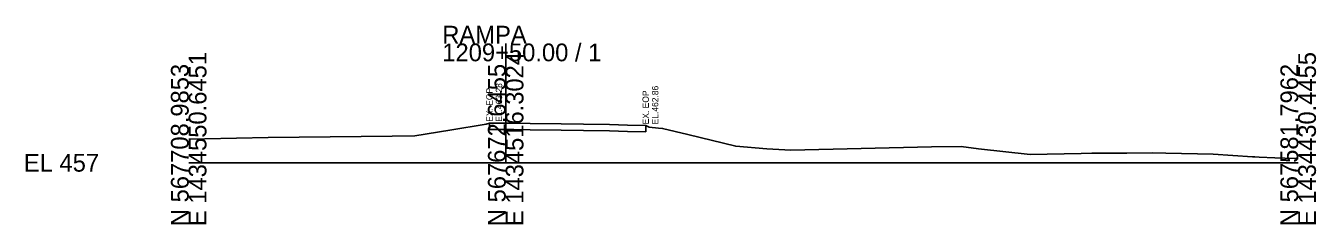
# Model space of a CAD drawing. Extents: x 1431908 to 1449087, y 567604 to 577825.
# Drawn here: x 1432908 to 1433111.5, y 575852.5 to 575883.8 of the extents above; entities that cross this region are included whole.
import ezdxf

# ---------------------------------------------------------------- set-up
doc = ezdxf.new("R2010")
doc.units = 0
for name, color, linetype in [('DESIGN - SHEET - Light Grid', 7, 'Continuous'), ('SURVEY - GROUND - Existing Pavement Layer', 7, 'Continuous'), ('SURVEY - GROUND - Existing Pavement Text', 7, 'Continuous'), ('SURVEY - GROUND - Top of Ground', 7, 'Continuous')]:
    doc.layers.add(name, color=color, linetype=linetype)

msp = doc.modelspace()

# ---------------------------------------------------------------- linework, layer by layer
at = {"layer": 'DESIGN - SHEET - Light Grid'}
for p, q in [((1432983.66, 575862.16), (1432983.66, 575880.98)), ((1432933.66, 575862.16), (1432983.66, 575862.16)), ((1432983.66, 575862.16), (1433108.66, 575862.16))]:
    msp.add_line(p, q, dxfattribs=at)
at = {"layer": 'SURVEY - GROUND - Existing Pavement Layer'}
for p, q in [((1432981.1, 575867.43), (1432981.1, 575868.43)), ((1432981.1, 575867.43), (1432983.66, 575867.42)), ((1432983.66, 575867.42), (1432984.08, 575867.42)), ((1432984.08, 575867.42), (1432984.97, 575867.41)), ((1432984.97, 575867.41), (1432987.51, 575867.38)), ((1432987.51, 575867.38), (1432992.4, 575867.33)), ((1432992.4, 575867.33), (1432995.93, 575867.26)), ((1432995.93, 575867.26), (1433000.05, 575867.19)), ((1433000.05, 575867.19), (1433002.86, 575867.11)), ((1433002.86, 575867.11), (1433005.74, 575867.02)), ((1433005.74, 575868.02), (1433005.74, 575867.02))]:
    msp.add_line(p, q, dxfattribs=at)
at = {"layer": 'SURVEY - GROUND - Top of Ground'}
msp.add_lwpolyline([(1432933.66, 575865.9), (1432936.19, 575865.94), (1432946.21, 575866.13), (1432965.74, 575866.37), (1432969.32, 575866.41), (1432974.85, 575867.32), (1432980.6, 575868.25), (1432981.1, 575868.43), (1432983.66, 575868.42), (1432984.08, 575868.42), (1432984.97, 575868.41), (1432987.51, 575868.38), (1432992.4, 575868.33), (1432995.93, 575868.26), (1433000.05, 575868.19), (1433002.86, 575868.11), (1433005.74, 575868.02), (1433006.31, 575867.78), (1433007.75, 575867.64), (1433008.4, 575867.59), (1433012.41, 575866.61), (1433019.95, 575864.77), (1433024.85, 575864.36), (1433028.66, 575864.13), (1433050.81, 575864.66), (1433055.49, 575864.73), (1433058.23, 575864.37), (1433066.37, 575863.44), (1433074.42, 575863.62), (1433076.13, 575863.65), (1433081.62, 575863.69), (1433085.76, 575863.72), (1433087.8, 575863.67), (1433095.24, 575863.52), (1433101.45, 575863.1), (1433101.84, 575863.08), (1433102.49, 575863.05), (1433104.98, 575862.92), (1433106.58, 575862.89), (1433108.66, 575862.86)], dxfattribs=at)

# ---------------------------------------------------------------- texts
at = {"layer": 'DESIGN - SHEET - Light Grid'}
for s, p in [('RAMPA', (1432973.66, 575880.98)), ('1209+50.00 / 1', (1432973.66, 575878.18)), ('EL 457', (1432907.66, 575860.76))]:
    msp.add_text(s, height=2.8, dxfattribs=at).set_placement(p)
for s, p in [('E 1434550.6451', (1432936.46, 575852.16)), ('E 1434516.3024', (1432986.46, 575852.16)), ('E 1434430.4455', (1433111.46, 575852.16)), ('N 567708.9853', (1432933.66, 575852.16)), ('N 567672.6455', (1432983.66, 575852.16)), ('N 567581.7962', (1433108.66, 575852.16))]:
    msp.add_text(s, height=2.8, rotation=90, dxfattribs=at).set_placement(p)
at = {"layer": 'SURVEY - GROUND - Existing Pavement Text'}
for s, p in [('EX. EOP', (1432981.6, 575868.63)), ('EL.463.28', (1432983.1, 575868.63)), ('EX. EOP', (1433006.24, 575868.22)), ('EL.462.86', (1433007.74, 575868.22))]:
    msp.add_text(s, height=1, rotation=90, dxfattribs=at).set_placement(p)

doc.saveas('drawing.dxf')
